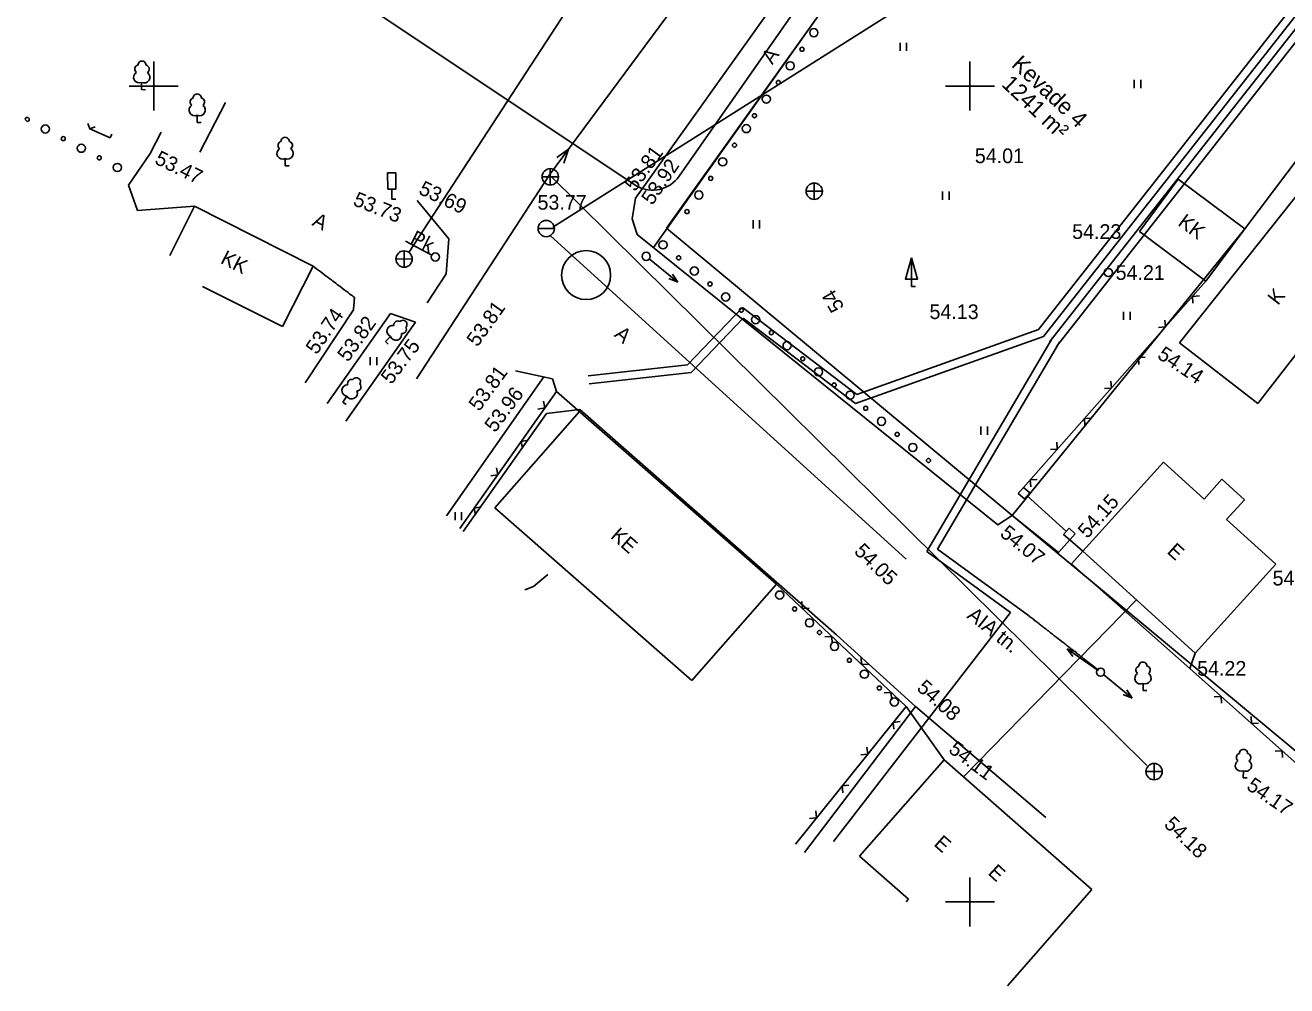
# Model space of a CAD drawing. Extents: x -2270 to -2134, y 846 to 969.
# Drawn here: x -2270.2 to -2193, y 846.4 to 905.3 of the extents above; entities that cross this region are included whole.
import ezdxf

# ---------------------------------------------------------------- set-up
doc = ezdxf.new("R2010")
doc.units = 0
for name, color, linetype in [('Level 10', 7, 'Continuous'), ('Level 11', 7, 'Continuous'), ('Level 12', 7, 'Continuous'), ('Level 15', 7, 'Continuous'), ('Level 16', 7, 'Continuous'), ('Level 18', 7, 'Continuous'), ('Level 19', 7, 'Continuous'), ('Level 20', 7, 'Continuous'), ('Level 21', 7, 'Continuous'), ('Level 32', 7, 'Continuous'), ('Level 34', 7, 'Continuous'), ('Level 4', 7, 'Continuous'), ('Level 45', 7, 'Continuous'), ('Level 6', 7, 'Continuous'), ('Level 63', 7, 'Continuous'), ('Level 7', 7, 'Continuous'), ('Level 8', 7, 'Continuous'), ('Level 9', 7, 'Continuous')]:
    doc.layers.add(name, color=color, linetype=linetype)

# ---------------------------------------------------------------- blocks, each defined once
blk = doc.blocks.new('31')
at = {"layer": 'Level 63'}
for p, q in [((0, 0.0176), (0, 0)), ((0, 0), (0.0096, 0))]:
    blk.add_line(p, q, dxfattribs=at)
for centre, radius, start, end in [((0, 0.06), 0.01, 359.8604, 180.8406), ((-0.006, 0.0303), 0.014, 122.2165, 294.8474), ((-0.0074, 0.0502), 0.01, 104.8801, 233.1553), ((0.0058, 0.0303), 0.014, 245.1526, 56.0466), ((0.0079, 0.0502), 0.01, 304.5704, 78.153)]:
    blk.add_arc(centre, radius, start, end, dxfattribs=at)
blk = doc.blocks.new('81')
at = {"layer": 'Level 63'}
for p, q in [((-0.02, 0), (0.02, 0)), ((0, 0.02), (0, -0.02))]:
    blk.add_line(p, q, dxfattribs=at)
blk.add_circle((0, 0), 0.02, dxfattribs=at)
blk = doc.blocks.new('65')
at = {"layer": 'Level 63'}
for p, q in [((0.01, 0.06429), (0, 0.05429)), ((0, 0.05429), (0.01, 0.04429)), ((0, 0.05429), (0, 0)), ((0.01, 0), (0, 0))]:
    blk.add_line(p, q, dxfattribs=at)
blk = doc.blocks.new('410')
at = {"layer": 'Level 63'}
blk.add_text('A', height=0.036, dxfattribs=at).set_placement((-0.00087, 0.00021))
blk = doc.blocks.new('HAKA')
at = {"layer": 'Level 63'}
for q in [(-0.012, 0.012), (0.012, 0.012)]:
    blk.add_line((0, 0), q, dxfattribs=at)
blk = doc.blocks.new('41')
at = {"layer": 'Level 63'}
for p, q in [((-0.00772, -0.00991), (-0.00772, 0.01009)), ((0.00828, -0.00991), (0.00828, 0.01009))]:
    blk.add_line(p, q, dxfattribs=at)
blk = doc.blocks.new('16')
at = {"layer": 'Level 63'}
for p, q in [((0, 0.06), (0, -0.06)), ((-0.06, 0), (0.06, 0))]:
    blk.add_line(p, q, dxfattribs=at)

msp = doc.modelspace()

# ---------------------------------------------------------------- linework, layer by layer
at = {"layer": 'Level 10'}
for p, q in [((-2197.909, 889.625), (-2209.08, 876.983)), ((-2198.737, 888.689), (-2198.314, 888.715)), ((-2198.737, 888.689), (-2198.711, 888.265)), ((-2200.392, 886.815), (-2200.419, 887.239)), ((-2200.392, 886.815), (-2200.816, 886.789)), ((-2202.048, 884.942), (-2201.625, 884.968)), ((-2202.048, 884.942), (-2202.022, 884.518)), ((-2203.703, 883.068), (-2203.73, 883.492)), ((-2243.611, 874.467), (-2237.693, 882.868)), ((-2203.703, 883.068), (-2204.127, 883.042)), ((-2238.412, 881.847), (-2238.83, 881.775)), ((-2238.412, 881.847), (-2238.485, 882.265)), ((-2205.358, 881.195), (-2204.935, 881.221)), ((-2205.358, 881.195), (-2205.332, 880.771)), ((-2207.014, 879.321), (-2207.04, 879.745)), ((-2207.014, 879.321), (-2207.437, 879.295)), ((-2208.669, 877.448), (-2208.246, 877.474)), ((-2208.669, 877.448), (-2208.643, 877.024)), ((-2208.866, 876.466), (-2206.461, 874.284)), ((-2216.281, 863.555), (-2224.222, 871.043)), ((-2222.647, 869.558), (-2222.66, 869.982)), ((-2222.647, 869.558), (-2222.223, 869.571)), ((-2220.828, 867.843), (-2221.253, 867.831)), ((-2220.828, 867.843), (-2220.816, 867.419)), ((-2219.01, 866.128), (-2219.022, 866.552)), ((-2198.898, 865.889), (-2198.56, 866.814)), ((-2219.01, 866.128), (-2218.586, 866.14)), ((-2184.942, 853.431), (-2198.898, 865.889)), ((-2217.191, 864.413), (-2217.615, 864.4)), ((-2217.191, 864.413), (-2217.179, 863.989)), ((-2216.281, 863.555), (-2223.06, 855.122)), ((-2217.064, 862.581), (-2216.643, 862.627)), ((-2217.064, 862.581), (-2217.019, 862.159))]:
    msp.add_line(p, q, dxfattribs=at)
at = {"layer": 'Level 11'}
for p, q in [((-2238.079, 896.515), (-2238.074, 895.515)), ((-2238.576, 896.013), (-2237.576, 896.017)), ((-2222.406, 895.134), (-2221.406, 895.134)), ((-2221.906, 895.634), (-2221.906, 894.634)), ((-2247.025, 891.477), (-2247.028, 890.477)), ((-2247.526, 890.979), (-2246.526, 890.976))]:
    msp.add_line(p, q, dxfattribs=at)
for centre in [(-2238.076, 896.015), (-2221.906, 895.134), (-2247.026, 890.977)]:
    msp.add_circle(centre, 0.5, dxfattribs=at)
at = {"layer": 'Level 12'}
for p, q in [((-2232.006, 890.98), (-2230.264, 889.556)), ((-2230.264, 889.556), (-2230.814, 889.777)), ((-2230.264, 889.556), (-2230.59, 890.051)), ((-2206.418, 867.082), (-2205.852, 866.904)), ((-2204.569, 865.799), (-2206.418, 867.082)), ((-2206.418, 867.082), (-2206.054, 866.613)), ((-2204.171, 865.498), (-2202.431, 864.071)), ((-2202.431, 864.071), (-2202.981, 864.293)), ((-2202.431, 864.071), (-2202.756, 864.567))]:
    msp.add_line(p, q, dxfattribs=at)
for centre in [(-2232.199, 891.138), (-2203.892, 890.148), (-2204.364, 865.657), (-2204.364, 865.657)]:
    msp.add_circle(centre, 0.25, dxfattribs=at)
at = {"layer": 'Level 15'}
for p, q in [((-2246.259, 883.64), (-2238.128, 896.128)), ((-2238.128, 896.128), (-2201.527, 859.945)), ((-2197.909, 889.625), (-2209.08, 876.982)), ((-2198.737, 888.688), (-2198.726, 888.701)), ((-2198.737, 888.688), (-2198.725, 888.677)), ((-2200.392, 886.815), (-2200.405, 886.827)), ((-2200.392, 886.815), (-2200.404, 886.803)), ((-2202.047, 884.941), (-2202.036, 884.954)), ((-2202.047, 884.941), (-2202.035, 884.93)), ((-2203.703, 883.068), (-2203.716, 883.08)), ((-2203.703, 883.068), (-2203.715, 883.056)), ((-2238.412, 881.847), (-2238.426, 881.857)), ((-2238.412, 881.847), (-2238.423, 881.834)), ((-2205.358, 881.195), (-2205.347, 881.208)), ((-2205.358, 881.195), (-2205.346, 881.184)), ((-2207.014, 879.321), (-2207.027, 879.333)), ((-2207.014, 879.321), (-2207.026, 879.309)), ((-2208.669, 877.448), (-2208.658, 877.461)), ((-2208.669, 877.448), (-2208.657, 877.437)), ((-2208.866, 876.466), (-2206.461, 874.283)), ((-2222.647, 869.558), (-2222.66, 869.57)), ((-2222.647, 869.558), (-2222.636, 869.57)), ((-2220.828, 867.843), (-2220.84, 867.831)), ((-2220.828, 867.843), (-2220.816, 867.831)), ((-2219.009, 866.128), (-2219.022, 866.14)), ((-2219.009, 866.128), (-2218.998, 866.14)), ((-2217.19, 864.413), (-2217.202, 864.401)), ((-2217.19, 864.413), (-2217.178, 864.401)), ((-2217.064, 862.581), (-2217.054, 862.594)), ((-2217.064, 862.581), (-2217.052, 862.57))]:
    msp.add_line(p, q, dxfattribs=at)
for points in [[(-2238.128, 896.128), (-2210.494, 933.465), (-2189.567, 964.235)], [(-2237.673, 897.198), (-2236.957, 897.714), (-2237.235, 896.86)]]:
    msp.add_lwpolyline(points, dxfattribs=at)
at = {"layer": 'Level 16'}
for p, q in [((-2237.916, 892.929), (-2213.477, 908.38)), ((-2212.369, 903.074), (-2212.369, 900.074)), ((-2213.869, 901.574), (-2210.869, 901.574))]:
    msp.add_line(p, q, dxfattribs=at)
at = {"layer": 'Level 18'}
for p, q in [((-2246.733, 891.382), (-2217.016, 937.014)), ((-2222.406, 895.134), (-2221.406, 895.134)), ((-2221.906, 895.634), (-2221.907, 894.634)), ((-2212.756, 859.236), (-2202.156, 870.082))]:
    msp.add_line(p, q, dxfattribs=at)
msp.add_lwpolyline([(-2239.626, 870.716), (-2239.58, 870.724), (-2239.096, 870.915), (-2238.232, 871.65)], dxfattribs=at)
msp.add_circle((-2221.906, 895.134), 0.5, dxfattribs=at)
at = {"layer": 'Level 19'}
for p, q in [((-2230.178, 896.053), (-2203.961, 933.613)), ((-2220.006, 912.755), (-2232.856, 894.697)), ((-2232.804, 895.458), (-2257.828, 912.171)), ((-2232.856, 894.697), (-2233.067, 893.446)), ((-2233.067, 893.446), (-2232.75, 892.478)), ((-2247.854, 887.635), (-2251.745, 882.125)), ((-2246.333, 887.098), (-2247.854, 887.635)), ((-2250.595, 881.042), (-2246.333, 887.098)), ((-2237.946, 883.635), (-2240.204, 884.134))]:
    msp.add_line(p, q, dxfattribs=at)
for points in [[(-2246.233, 894.558), (-2244.296, 892.209), (-2244.452, 890.067), (-2245.624, 888.3)], [(-2206.247, 873.767), (-2206.932, 872.993), (-2209.781, 875.264), (-2210.65, 874.685), (-2232.75, 892.478)]]:
    msp.add_lwpolyline(points, dxfattribs=at)
msp.add_arc((-2231.818, 897.198), 2, 240.46318, 325.08534, dxfattribs=at)
at = {"layer": 'Level 20'}
msp.add_line((-2216.275, 872.584), (-2238.078, 892.41), dxfattribs=at)
at = {"layer": 'Level 21'}
for p, q in [((-2208.173, 886.648), (-2189.276, 910.702)), ((-2207.864, 886.227), (-2188.912, 910.359)), ((-2207.466, 885.925), (-2188.549, 910.016)), ((-2207.068, 885.622), (-2188.185, 909.673)), ((-2229.676, 884.498), (-2226.305, 888.011)), ((-2226.305, 888.011), (-2219.295, 882.682)), ((-2229.441, 884.021), (-2226.253, 887.344)), ((-2226.253, 887.344), (-2219.382, 882.12)), ((-2219.295, 882.682), (-2208.173, 886.648)), ((-2219.382, 882.12), (-2207.864, 886.227)), ((-2207.311, 886.141), (-2215.011, 873.057)), ((-2206.88, 885.887), (-2214.35, 873.194)), ((-2235.75, 883.828), (-2229.676, 884.498)), ((-2235.696, 883.331), (-2229.441, 884.021)), ((-2215.011, 873.057), (-2209.885, 869.318)), ((-2214.35, 873.194), (-2208.782, 869.132)), ((-2209.885, 869.318), (-2220.731, 855.269))]:
    msp.add_line(p, q, dxfattribs=at)
msp.add_open_spline([(-2208.768, 869.122), (-2207.339, 868.005), (-2205.909, 866.888), (-2204.479, 865.771)], degree=2, dxfattribs=at)
at = {"layer": 'Level 34'}
msp.add_line((-2238.824, 892.846), (-2237.824, 892.846), dxfattribs=at)
for centre, radius in [((-2238.324, 892.846), 0.5), ((-2235.877, 889.991), 1.5)]:
    msp.add_circle(centre, radius, dxfattribs=at)
at = {"layer": 'Level 45'}
for p, q in [((-2230.947, 892.878), (-2206.455, 927.192)), ((-2195.519, 892.834), (-2173.639, 921.954)), ((-2230.947, 892.878), (-2184.939, 854.594)), ((-2209.779, 875.264), (-2195.519, 892.834)), ((-2243.402, 874.27), (-2238.3, 881.511)), ((-2236.264, 881.746), (-2238.3, 881.511)), ((-2220.534, 867.938), (-2236.264, 881.746)), ((-2220.534, 867.938), (-2215.7, 863.545)), ((-2222.505, 854.599), (-2215.7, 863.545)), ((-2215.7, 863.545), (-2207.719, 856.754))]:
    msp.add_line(p, q, dxfattribs=at)
at = {"layer": 'Level 6'}
for p, q in [((-2188.502, 899.738), (-2199.532, 885.847)), ((-2199.602, 895.869), (-2201.989, 892.659)), ((-2195.522, 892.835), (-2199.602, 895.869)), ((-2259.864, 894.212), (-2261.386, 891.2)), ((-2259.864, 894.212), (-2252.607, 890.545)), ((-2197.909, 889.625), (-2201.989, 892.659)), ((-2197.909, 889.625), (-2195.522, 892.835)), ((-2194.734, 882.129), (-2187.102, 891.977)), ((-2252.607, 890.545), (-2254.483, 886.832)), ((-2259.368, 889.3), (-2254.483, 886.832)), ((-2199.532, 885.847), (-2194.734, 882.129)), ((-2224.222, 871.043), (-2237.693, 882.868)), ((-2236.284, 881.631), (-2241.463, 875.731)), ((-2205.449, 873.075), (-2200.513, 878.529)), ((-2198.027, 876.269), (-2200.513, 878.529)), ((-2198.027, 876.269), (-2196.926, 877.485)), ((-2195.542, 876.228), (-2196.926, 877.485)), ((-2209.408, 876.605), (-2209.08, 876.983)), ((-2209.408, 876.605), (-2209.03, 876.277)), ((-2209.08, 876.983), (-2208.703, 876.655)), ((-2209.03, 876.277), (-2208.703, 876.655)), ((-2229.401, 865.144), (-2241.463, 875.731)), ((-2196.643, 875.012), (-2195.542, 876.228)), ((-2193.624, 872.268), (-2196.643, 875.012)), ((-2206.625, 874.095), (-2206.297, 874.473)), ((-2206.625, 874.095), (-2206.247, 873.767)), ((-2206.297, 874.473), (-2205.92, 874.145)), ((-2206.247, 873.767), (-2205.92, 874.145)), ((-2198.56, 866.814), (-2205.449, 873.075)), ((-2198.56, 866.814), (-2193.624, 872.268)), ((-2224.222, 871.043), (-2229.401, 865.144)), ((-2213.951, 860.285), (-2219.13, 854.386)), ((-2204.895, 852.336), (-2213.951, 860.285)), ((-2216.124, 851.747), (-2219.13, 854.386)), ((-2216.124, 851.747), (-2216.275, 851.574)), ((-2204.895, 852.336), (-2210.074, 846.437)), ((-2204.895, 852.336), (-2205.564, 851.574))]:
    msp.add_line(p, q, dxfattribs=at)
at = {"layer": 'Level 63'}
msp.add_line((-2217, 863.831), (-2217, 863.831), dxfattribs=at)
at = {"layer": 'Level 7'}
for p, q in [((-2217.784, 911.32), (-2231.76, 891.681)), ((-2259.534, 897.519), (-2257.966, 900.577)), ((-2262.576, 897.453), (-2261.91, 898.745)), ((-2263.911, 895.494), (-2262.576, 897.453)), ((-2263.911, 895.494), (-2263.35, 893.954)), ((-2263.35, 893.954), (-2259.864, 894.212)), ((-2250.129, 887.86), (-2253.098, 883.398)), ((-2238.463, 883.749), (-2244.425, 875.234)), ((-2237.946, 883.635), (-2237.693, 882.868)), ((-2205.449, 873.075), (-2206.247, 873.767)), ((-2206.141, 872.294), (-2205.449, 873.075)), ((-2198.898, 865.889), (-2206.141, 872.294)), ((-2213.951, 860.285), (-2216.281, 863.555)), ((-2204.895, 852.336), (-2213.951, 860.285))]:
    msp.add_line(p, q, dxfattribs=at)
msp.add_open_spline([(-2252.607, 890.545), (-2250.068, 888.619), (-2250.068, 888.619), (-2250.129, 887.86)], degree=2, dxfattribs=at)
at = {"layer": 'Level 8'}
for p, q in [((-2248.039, 896.259), (-2247.539, 896.262)), ((-2248.039, 896.259), (-2248.034, 895.259)), ((-2247.539, 896.262), (-2247.534, 895.262)), ((-2248.034, 895.259), (-2247.534, 895.262)), ((-2247.784, 895.26), (-2247.78, 894.653)), ((-2247.53, 894.655), (-2247.78, 894.653)), ((-2245.338, 891.216), (-2246.943, 892.078))]:
    msp.add_line(p, q, dxfattribs=at)
for centre in [(-2245.117, 891.098), (-2203.892, 890.148)]:
    msp.add_circle(centre, 0.25, dxfattribs=at)
at = {"layer": 'Level 9'}
for p, q in [((-2221.927, 904.849), (-2221.927, 904.849)), ((-2216.649, 903.736), (-2216.649, 904.236)), ((-2216.249, 903.736), (-2216.249, 904.236)), ((-2202.302, 901.454), (-2202.302, 901.954)), ((-2201.902, 901.454), (-2201.902, 901.954)), ((-2226.063, 898.971), (-2226.063, 898.971)), ((-2264.596, 896.587), (-2264.596, 896.587)), ((-2254.317, 897.132), (-2254.317, 896.692)), ((-2254.317, 896.692), (-2254.077, 896.692)), ((-2214.04, 894.609), (-2214.04, 895.109)), ((-2213.64, 894.609), (-2213.64, 895.109)), ((-2225.648, 892.849), (-2225.648, 893.349)), ((-2225.248, 892.849), (-2225.248, 893.349)), ((-2231.17, 891.847), (-2231.17, 891.847)), ((-2215.944, 891.053), (-2215.944, 889.303)), ((-2216.314, 889.733), (-2215.574, 889.733)), ((-2215.944, 889.303), (-2215.694, 889.303)), ((-2225.488, 887.265), (-2225.488, 887.265)), ((-2202.954, 887.243), (-2202.954, 887.743)), ((-2202.554, 887.243), (-2202.554, 887.743)), ((-2219.707, 882.632), (-2219.707, 882.632)), ((-2211.693, 880.203), (-2211.693, 880.703)), ((-2211.293, 880.203), (-2211.293, 880.703)), ((-2201.764, 864.966), (-2201.761, 864.526)), ((-2201.761, 864.526), (-2201.521, 864.528))]:
    msp.add_line(p, q, dxfattribs=at)
msp.add_lwpolyline([(-2270.237, 899.532), (-2270.108, 899.41)], dxfattribs=at)
msp.add_lwpolyline([(-2215.944, 891.053), (-2215.574, 889.733), (-2216.314, 889.733)], close=True, dxfattribs=at)
for centre, radius in [((-2221.927, 904.849), 0.25), ((-2222.654, 903.831), 0.125), ((-2223.381, 902.814), 0.25), ((-2224.108, 901.796), 0.125), ((-2224.835, 900.778), 0.25), ((-2225.562, 899.76), 0.125), ((-2269.009, 898.946), 0.25), ((-2226.063, 898.971), 0.25), ((-2267.906, 898.356), 0.125), ((-2266.803, 897.766), 0.25), ((-2226.79, 897.953), 0.125), ((-2265.7, 897.177), 0.125), ((-2264.596, 896.587), 0.25), ((-2227.517, 896.936), 0.25), ((-2228.244, 895.918), 0.125), ((-2228.971, 894.9), 0.25), ((-2229.698, 893.882), 0.125), ((-2231.17, 891.847), 0.25), ((-2230.209, 891.047), 0.125), ((-2229.248, 890.246), 0.25), ((-2228.287, 889.445), 0.125), ((-2227.326, 888.645), 0.25), ((-2226.365, 887.844), 0.125), ((-2225.488, 887.265), 0.25), ((-2224.528, 886.464), 0.125), ((-2223.567, 885.664), 0.25), ((-2222.606, 884.863), 0.125), ((-2221.645, 884.062), 0.25), ((-2220.684, 883.262), 0.125), ((-2219.707, 882.632), 0.25), ((-2218.747, 881.832), 0.125), ((-2217.786, 881.031), 0.25), ((-2216.825, 880.23), 0.125), ((-2215.864, 879.43), 0.25), ((-2214.903, 878.629), 0.125), ((-2224.024, 870.381), 0.25), ((-2223.108, 869.53), 0.125), ((-2222.192, 868.678), 0.25), ((-2221.581, 868.088), 0.125), ((-2220.665, 867.237), 0.25), ((-2219.749, 866.385), 0.125), ((-2218.833, 865.534), 0.25), ((-2217.917, 864.682), 0.125), ((-2217.001, 863.831), 0.25)]:
    msp.add_circle(centre, radius, dxfattribs=at)
for centre, radius, start, end in [((-2270.112, 899.535), 0.125, 271.73786, 181.72267), ((-2254.503, 897.947), 0.25, 104.88012, 233.15525), ((-2254.317, 898.192), 0.25, 359.8604, 180.8406), ((-2254.119, 897.947), 0.25, 304.57036, 78.15304), ((-2254.467, 897.451), 0.35, 122.21649, 294.84737), ((-2254.172, 897.451), 0.35, 245.15263, 56.0466), ((-2201.915, 865.284), 0.35, 122.53979, 295.17068), ((-2201.954, 865.78), 0.25, 105.20342, 233.47856), ((-2201.77, 866.026), 0.25, 0.1837, 181.16391), ((-2201.621, 865.286), 0.35, 245.47593, 56.36991), ((-2201.57, 865.782), 0.25, 304.89367, 78.47635)]:
    msp.add_arc(centre, radius, start, end, dxfattribs=at)

# ---------------------------------------------------------------- block references
at = {"layer": 'Level 10'}
for p, xscale, yscale, rotation in [((-2239.852, 879.803), 25, 25, -125.15940000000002), ((-2241.291, 877.759), 25, 25, 54.84060000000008), ((-2242.731, 875.715), 25, 25, -125.15940000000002), ((-2196.977, 864.174), 24.999999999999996, 25.000000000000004, 138.24720000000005), ((-2195.112, 862.51), 24.999999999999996, 25.000000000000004, -41.75280000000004), ((-2218.631, 860.632), 25, 25, 51.20729999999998), ((-2193.247, 860.845), 24.999999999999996, 25.000000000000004, 138.24720000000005), ((-2220.197, 858.684), 25.000000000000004, 24.999999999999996, -128.79270000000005), ((-2221.763, 856.735), 25, 25, 51.20729999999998)]:
    msp.add_blockref('HAKA', p, dxfattribs=dict(at, xscale=xscale, yscale=yscale, rotation=rotation))
at = {"layer": 'Level 11', "xscale": 25.000000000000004, "yscale": 25, "rotation": -0.08484627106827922}
msp.add_blockref('81', (-2201.084, 859.563), dxfattribs=at)
at = {"layer": 'Level 15'}
for p, xscale, yscale, rotation in [((-2239.851, 879.803), 1.0000054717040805, 1.0000054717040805, -81.61916784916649), ((-2241.291, 877.759), 1.0000054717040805, 1.0000054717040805, 98.38083215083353), ((-2242.731, 875.715), 1.0000054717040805, 1.0000054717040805, -81.61916784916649), ((-2218.63, 860.632), 1.0000000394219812, 1.0000000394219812, 94.74772199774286), ((-2220.197, 858.684), 1.0000000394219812, 1.0000000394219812, -85.25227800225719), ((-2221.763, 856.735), 1.0000000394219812, 1.0000000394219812, 94.74772199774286)]:
    msp.add_blockref('HAKA', p, dxfattribs=dict(at, xscale=xscale, yscale=yscale, rotation=rotation))
at = {"layer": 'Level 16', "xscale": 25, "yscale": 25}
for p in [(-2262.369, 901.574), (-2212.369, 851.574), (-2212.369, 851.574)]:
    msp.add_blockref('16', p, dxfattribs=at)
at = {"layer": 'Level 7', "xscale": 24.999999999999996, "yscale": 25.000000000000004, "rotation": -27.15545694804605}
msp.add_blockref('410', (-2252.703, 893.052), dxfattribs=at)
at = {"layer": 'Level 8', "xscale": 25, "yscale": 25, "rotation": 66.07520912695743}
msp.add_blockref('65', (-2265.033, 898.408), dxfattribs=at)
at = {"layer": 'Level 9'}
for p, xscale, yscale, rotation in [((-2263.112, 901.359), 24.999999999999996, 25.000000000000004, -0.989815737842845), ((-2248.171, 885.923), 24.999999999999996, 25.000000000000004, -45.47395648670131), ((-2250.774, 882.201), 25, 25, -33.28963103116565), ((-2195.621, 859.174), 25.000000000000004, 24.999999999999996, -0.5087537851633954)]:
    msp.add_blockref('31', p, dxfattribs=dict(at, xscale=xscale, yscale=yscale, rotation=rotation))
at = {"layer": 'Level 9', "xscale": 25, "yscale": 25}
for name, p in [('31', (-2259.699, 899.347)), ('41', (-2248.912, 884.716)), ('41', (-2243.715, 875.214))]:
    msp.add_blockref(name, p, dxfattribs=at)

# ---------------------------------------------------------------- texts
at = {"layer": 'Level 19'}
msp.add_text('A', height=0.9, rotation=319.48693, dxfattribs=at).set_placement((-2234.207, 886.271))
at = {"layer": 'Level 32'}
msp.add_text('54', height=0.9, rotation=120, dxfattribs=at).set_placement((-2220.042, 888.034))
at = {"layer": 'Level 4'}
for s, height, rotation, p in [('53.47', 0.8995, 334.06379, (-2262.368, 896.852)), ('53.81', 0.9, 53.90492, (-2232.88, 895.063)), ('53.92', 0.9, 55.71355, (-2231.821, 894.228)), ('53.69', 0.9, 334.67472, (-2246.197, 894.997)), ('53.73', 0.9, 338.1911, (-2250.21, 894.296)), ('53.74', 0.8995, 55.6612, (-2252.383, 885.071)), ('53.81', 0.8995, 54.37666, (-2242.538, 885.545)), ('53.82', 0.9, 54.04314, (-2250.461, 884.62)), ('53.75', 0.9, 52.90574, (-2247.81, 883.24)), ('54.14', 0.9, 326.42371, (-2200.949, 884.938)), ('53.81', 0.9, 53.79023, (-2242.424, 881.591)), ('53.96', 0.9, 53.2643, (-2241.456, 880.293)), ('54.15', 0.9, 48.46737, (-2205.171, 873.802)), ('54.07', 0.9, 320.98596, (-2210.584, 874.052)), ('54.05', 0.9, 315.83172, (-2219.512, 873.002)), ('54.08', 0.9, 318.19031, (-2215.682, 864.609)), ('54.11', 0.8995, 323.03249, (-2213.737, 860.793)), ('54.17', 0.9, 325.60957, (-2195.487, 858.526)), ('54.18', 0.8995, 315.92479, (-2200.533, 856.264))]:
    msp.add_text(s, height=height, rotation=rotation, dxfattribs=at).set_placement(p)
for s, p in [('54.01', (-2212.066, 896.853)), ('53.77', (-2238.855, 894.003)), ('54.23', (-2206.104, 892.209)), ('54.21', (-2203.442, 889.698)), ('54.13', (-2214.844, 887.298)), ('54.13', (-2214.844, 887.298)), ('54.22', (-2193.826, 870.971)), ('54.22', (-2198.448, 865.439))]:
    msp.add_text(s, height=0.9, dxfattribs=at).set_placement(p)
at = {"layer": 'Level 45'}
for s, p in [('Kevade 4', (-2209.879, 902.822)), ('1241 m²', (-2210.484, 901.621))]:
    msp.add_text(s, height=1, rotation=316.73027, dxfattribs=at).set_placement(p)
at = {"layer": 'Level 6'}
for s, height, rotation, p in [('KK', 0.9, 323.36449, (-2199.688, 893.085)), ('KK', 0.8995, 333.19229, (-2258.332, 890.752)), ('K', 0.9, 52.22882, (-2193.497, 888.092)), ('KE', 0.9, 318.72461, (-2234.434, 873.924)), ('E', 0.899, 317.73418, (-2200.347, 872.992)), ('E', 0.9, 318.72461, (-2214.632, 855.068)), ('E', 0.9, 317.63999, (-2211.313, 853.3))]:
    msp.add_text(s, height=height, rotation=rotation, dxfattribs=at).set_placement(p)
at = {"layer": 'Level 7'}
for s, rotation, p in [('A', 54.95264, (-2224.471, 902.851)), ('AIA tn.', 321.35448, (-2212.602, 869.026))]:
    msp.add_text(s, height=0.9, rotation=rotation, dxfattribs=at).set_placement(p)
at = {"layer": 'Level 8'}
msp.add_text('Pk', height=0.9, rotation=333.31758, dxfattribs=at).set_placement((-2246.722, 891.972))

doc.saveas('drawing.dxf')
